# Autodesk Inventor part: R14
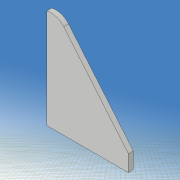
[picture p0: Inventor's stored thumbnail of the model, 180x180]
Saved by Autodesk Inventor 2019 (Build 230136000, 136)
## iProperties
Created: 2021-05
Part Number: R14
Material: 一般
Document SubType Name: Modeling
Designer: kikut
Density: 1 g/cm^3
Appearance: 既定
Mass: 0.06 g
Surface Area: 2.24 cm^2
Volume: 0.06 cm^3
Author: kikut
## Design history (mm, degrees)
sketch "スケッチ1"
  geometry: L1 (80, 60)-(-80, 60); L2 (-80, 60)-(-80, -60); L3 (-80, -60)-(80, -60); L4 (80, -60)-(80, 60); L5 (80, 60)-(-80, -60); L6 (-80, 60)-(80, -60); 1 further point
  constraints: 12 end point, 2 midpoint, 2 parallel, 1 horizontal, 1 perpendicular
  dimensions: "d0" = 160 distance of L2.end L3.end; "d1" = 120 distance of L1.end L2.end
extrude "押し出し1" new body sketch "スケッチ1" stored distance "d2" = 0.6; taper "d3" = 0 deg
sketch "スケッチ2"
  geometry: L1 (-140, 0)-(140, 0) reference; L2 (0, -54)-(20, -30); L3 (0, 54)-(20, 30); L4 (0, -3)-(6.514, -3); L5 (6.514, -3)-(16, -6); L6 (16, -6)-(24, -3); L7 (24, -3)-(33.716, -3); L8 (0, 3)-(6.514, 3); L9 (6.514, 3)-(16, 6); L10 (16, 6)-(24, 3); L11 (24, 3)-(33.716, 3); L12 (0, -98)-(0, 98) reference; L13 (-100, -70)-(100, -70); L14 (100, -70)-(100, 70); L15 (100, 70)-(-100, 70); L16 (-100, 70)-(-100, -70); L17 (-100, -70)-(100, 70); L18 (100, -70)-(-100, 70); A1 r 60 centre (54.312, 28.5) between (0, 54) and (0, 3); A2 r 60 centre (54.312, -28.5) between (0, -3) and (0, -54); A3 r 18.111 centre (18, -12) between (20, -30) and (33.716, -3); A4 r 18.111 centre (18, 12) between (33.716, 3) and (20, 30); 1 further point
  constraints: 32 end point, 8 point on circle, 8 symmetric about line, 4 centre point, 3 horizontal, 2 collinear, 2 midpoint, 2 parallel, 1 perpendicular
  dimensions: "d5" = 60 radius of A1; "d6" = 6 distance of L8.start L4.start; "d7" = 108 distance of L3.start L2.start; "d8" = 0 horizontal distance of L3.start L8.start; "d9" = 60 distance of L3.end L2.end; "d10" = 0 horizontal distance of point (0, 0) L3.start; "d11" = 20 horizontal distance of L3.start L3.end; "d12" = 24 distance of A4.centre A3.centre; "d13" = 6 distance of L11.end L7.end; "d14" = 12 distance of L9.end L5.end; "d15" = 16 distance from line of L12 L5.end; "d16" = 24 distance from line of L6.end L12; "d17" = 200 distance of L14.end L15.end; "d18" = 140 distance of L15.end L13.start; "d30" = 18 distance from line of L12 A4.centre
extrude "押し出し2" cut sketch "スケッチ2" stored distance "d19" = 10; taper "d20" = 0 deg
sketch "スケッチ3"
  geometry: L1 (49.705, -17.97)-(33.948, -15.191); L2 (33.948, -15.191)-(34.295, -13.222); L3 (34.295, -13.222)-(50.052, -16); L4 (50.052, -16)-(49.705, -17.97); L5 (49.705, -17.97)-(34.295, -13.222); L6 (33.948, -15.191)-(50.052, -16); L7 (50.052, 16)-(34.295, 13.222); L8 (34.295, 13.222)-(33.948, 15.191); L9 (33.948, 15.191)-(49.705, 17.97); L10 (49.705, 17.97)-(50.052, 16); L11 (50.052, 16)-(33.948, 15.191); L12 (34.295, 13.222)-(49.705, 17.97); L13 (-112, 0)-(112, 0) reference; L14 (0, -84)-(0, 84) reference; 3 further points
  constraints: 24 end point, 4 midpoint, 4 parallel, 2 perpendicular, 2 symmetric about line
  dimensions: "d21" = 2 distance of L3.end L1.start; "d22" = 2 distance of L9.end L7.start; "d23" = 16 distance of L8.end L9.end; "d24" = 42 distance from line of L14 point (42, 15.596); "d26" = 10 deg angle of L7 L13; "d62" = 16 distance from line of L3.end L13
extrude "押し出し3" join sketch "スケッチ3" distance "d27" = 0.6; taper "d28" = 0 deg
fillet "フィレット1" dims "d31" = 2
fillet "フィレット2" dims "d32" = 1
sketch "スケッチ6"
  geometry: L1 (-20, 60)-(80, 60); L2 (80, 60)-(80, -60); L3 (80, -60)-(-20, -60); L4 (-20, -60)-(-20, 60); L5 (-46.168, 0)-(93.832, 0) reference; L6 (0, -84)-(0, 84) reference; L7 (0, 40)-(10, 40); L8 (10, 40)-(10, 56); L9 (10, 56)-(0, 56); L10 (0, 56)-(0, 40); 1 further point
  constraints: 16 end point, 4 parallel, 2 horizontal, 2 perpendicular, 1 other
  dimensions: "d63" = 120 distance of L3.end L1.start; "d64" = 100 distance of L1.start L1.end; "d65" = 20 distance between parallel lines of L6 L4; "d66" = 10 distance of L8.end L9.end; "d73" = 16 distance of L9.end L7.start; "d74" = 40 distance between parallel lines of L7 L5; "d75" = 20 distance between parallel lines of L10 L4
extrude "押し出し4" cut sketch "スケッチ6" stored distance "d70" = 10; taper "d71" = 0 deg
node "ソリッド1"
